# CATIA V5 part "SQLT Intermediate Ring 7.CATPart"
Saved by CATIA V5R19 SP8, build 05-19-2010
Part number: SQLT Intermediate Ring 7
Publications: "Droite.1", "Plan.1", "Plan.2", "Droite.2", "Droite.3", "Droite.4", "Point.4", "Point.3"
Bounding box of the stored display mesh (mm): x -150 to 150, y 410 to 580, z 570 to 670
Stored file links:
  G:\EU_thinkMotion\CFAO_2010\MMS_groupe3\MMS_groupe3\A reprendre\fovide\fovide\SQLT Intermediate Ring 7.CATPart
  G:\EU_thinkMotion\CFAO_2010\MMS_groupe3\MMS_groupe3\A reprendre\fovide\fovide\fovide.CATProduct
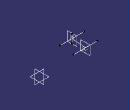
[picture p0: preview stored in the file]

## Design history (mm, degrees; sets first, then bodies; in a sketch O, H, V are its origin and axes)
Set1
  Point1 "Point.M": linked copy from another document
  Point2 "Point.N": linked copy from another document
Set2 "set SQLT Intermediate Ring 7"
  Line1: type PtPt, FirstPoint Point1, SecondPoint Point2
  Plane1: type OffsetPt, RefPlane yz-plane, RefPoint Point1
  Plane2: type OffsetPt, RefPlane yz-plane, RefPoint Point2
  Line2: type Normal, RefPoint Point2, RefSkin Plane2, Start -150, End 150
  Line3: type Normal, RefPoint Point1, RefSkin Plane1, Start -150, End 150
  Line4: type Normal, RefPoint Point2, RefSkin xy-plane, Start -50, End 50
  Point3: type OnCurve, Support Line3, Length 130
  Point4: type OnCurve, Support Line4, Length 29
Body1 (main body)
